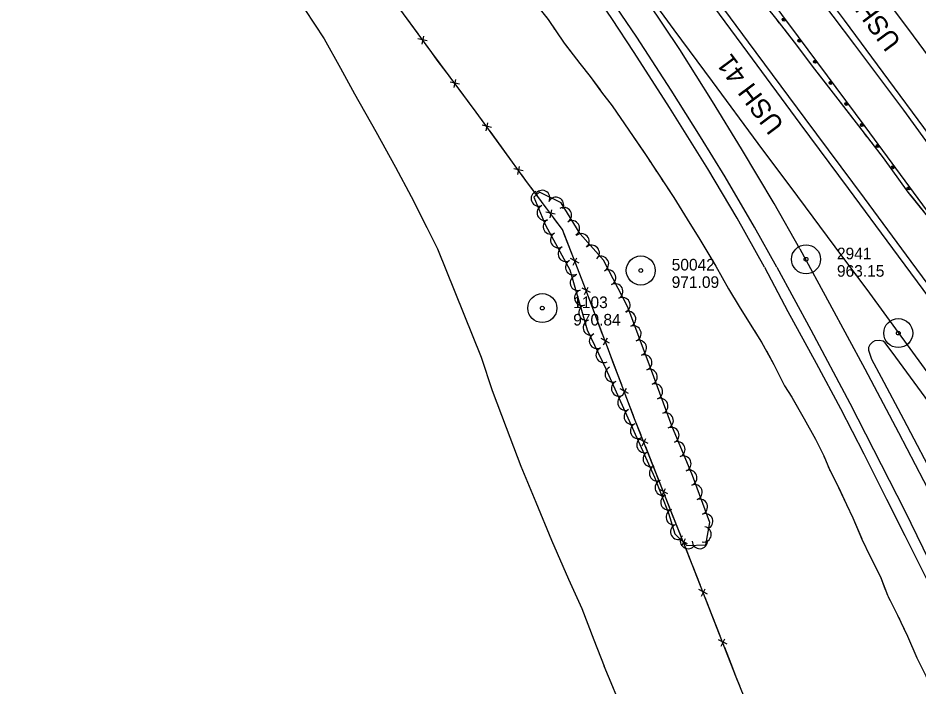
# Model space of a CAD drawing. Extents: x 353423 to 364002, y 127000 to 201942.
# Drawn here: x 358103.2 to 358569.3, y 133305.5 to 133651.2 of the extents above; entities that cross this region are included whole.
import ezdxf

# ---------------------------------------------------------------- set-up
doc = ezdxf.new("R2010")
doc.units = 0
for name, color, linetype in [('E_DTM_SlopeBottom', 7, 'Continuous'), ('E_DTM_SlopeTop', 7, 'Continuous'), ('E_FEN_Generic', 7, 'Continuous'), ('E_MISCPROP', 7, 'Continuous'), ('E_RDWY_AsphConc', 7, 'Continuous'), ('E_RW_IP', 7, 'Continuous'), ('E_STRUCT_WingWall', 7, 'Continuous')]:
    doc.layers.add(name, color=color, linetype=linetype)

msp = doc.modelspace()

# ---------------------------------------------------------------- linework, layer by layer
at = {"layer": 'E_DTM_SlopeBottom'}
for p, q in [((358314.93, 133639.42), (358310.13, 133640.52)), ((358312.21, 133637.66), (358313.14, 133641.78)), ((358331.53, 133617.07), (358326.71, 133618.11)), ((358328.83, 133615.27), (358329.7, 133619.41)), ((358348.11, 133594.66), (358343.3, 133595.76)), ((358345.4, 133592.89), (358346.31, 133597.02)), ((358364.53, 133572.15), (358359.72, 133573.25)), ((358361.81, 133570.38), (358362.72, 133574.51)), ((358378.43, 133548), (358379.3, 133552.14)), ((358381.12, 133549.8), (358376.3, 133550.84)), ((358393.46, 133524.54), (358389.1, 133526.84)), ((358390.38, 133523.53), (358392.33, 133527.28)), ((358399.34, 133509.27), (358394.99, 133511.6)), ((358396.25, 133508.28), (358398.23, 133512.02)), ((358409.2, 133483.22), (358404.86, 133485.55)), ((358406.11, 133482.23), (358408.09, 133485.97)), ((358419.07, 133457.16), (358414.72, 133459.49)), ((358415.98, 133456.17), (358417.95, 133459.91)), ((358429.12, 133431.21), (358424.74, 133433.47)), ((358426.05, 133430.17), (358427.97, 133433.94)), ((358439.38, 133405.3), (358435, 133407.57)), ((358436.3, 133404.27), (358438.22, 133408.04)), ((358449.63, 133379.4), (358445.25, 133381.66)), ((358446.56, 133378.37), (358448.48, 133382.13)), ((358456.76, 133352.45), (358458.69, 133356.21)), ((358459.83, 133353.47), (358455.46, 133355.75)), ((358470, 133327.53), (358465.63, 133329.81)), ((358466.92, 133326.51), (358468.85, 133330.27))]:
    msp.add_line(p, q, dxfattribs=at)
for points in [[(358395.86, 133513.55), (358384.88, 133541.86), (358366.84, 133566.02), (358340.28, 133602.45), (358317.22, 133633.32), (358288.05, 133673.47), (358260.09, 133711.16), (358241.9, 133736.28), (358214.23, 133774.01), (358187.7, 133809.56), (358155.49, 133852.29), (358125.09, 133893.37), (358100.76, 133925.95)], [(358310.34, 133642.79), (358303.68, 133651.95)], [(358320.11, 133629.44), (358317.22, 133633.32), (358314.21, 133637.46)], [(358326.89, 133620.38), (358320.11, 133629.44)], [(358336.79, 133607.13), (358330.83, 133615.1)], [(358343.51, 133598.02), (358340.28, 133602.45), (358336.79, 133607.13)], [(358353.26, 133584.65), (358347.39, 133592.7)], [(358359.93, 133575.51), (358353.26, 133584.65)], [(358369.72, 133562.18), (358366.84, 133566.02), (358363.8, 133570.19)], [(358376.49, 133553.1), (358369.72, 133562.18)], [(358385.79, 133539.52), (358384.88, 133541.86), (358380.42, 133547.83)], [(358389.88, 133528.97), (358385.79, 133539.52)], [(358395.86, 133513.55), (358392.26, 133522.83)], [(358725.68, 132583.74), (358758.72, 132601.14), (358713.52, 132713.04), (358681.9, 132791.31), (358650.4, 132872.83), (358629.23, 132926.93), (358604.43, 132991.52), (358574.94, 133062.09), (358555.62, 133108.12), (358526.45, 133181.6), (358502.84, 133241.38), (358474.77, 133310.6), (358451.95, 133368.81), (358422.16, 133444.07), (358395.86, 133513.55)], [(358401.65, 133498.26), (358398.12, 133507.57)], [(358405.66, 133487.67), (358401.65, 133498.26)], [(358411.51, 133472.2), (358407.99, 133481.52)], [(358415.52, 133461.61), (358411.51, 133472.2)], [(358421.38, 133446.15), (358417.85, 133455.46)], [(358425.51, 133435.61), (358422.16, 133444.07), (358421.38, 133446.15)], [(358431.6, 133420.23), (358427.93, 133429.49)], [(358435.77, 133409.71), (358431.6, 133420.23)], [(358441.85, 133394.33), (358438.19, 133403.58)], [(358446.02, 133383.8), (358441.85, 133394.33)], [(358452.11, 133368.42), (358451.95, 133368.81), (358448.44, 133377.68)], [(358456.24, 133357.88), (358452.11, 133368.42)], [(358462.27, 133342.48), (358458.64, 133351.75)], [(358466.4, 133331.94), (358462.27, 133342.48)], [(358472.43, 133316.54), (358468.8, 133325.81)], [(358476.62, 133306.02), (358474.77, 133310.6), (358472.43, 133316.54)]]:
    msp.add_lwpolyline(points, dxfattribs=at)
at = {"layer": 'E_DTM_SlopeTop'}
for points in [[(358410.49, 133650.87), (358393.29, 133676.15), (358374.38, 133703.52), (358357.7, 133727.25), (358339.4, 133753.66), (358320.07, 133781.45), (358301.48, 133808.44), (358281.55, 133836.86), (358261.2, 133866.08), (358242.57, 133892.57), (358225.2, 133917.27), (358205.5, 133944.9), (358188.78, 133968.59), (358169.81, 133995.17), (358151.76, 134021.41), (358131.7, 134049.96), (358113.99, 134074.7), (358093.46, 134101.84)], [(358426.57, 133830.55), (358455.05, 133791.84), (358479.58, 133758.58), (358507.67, 133720.69), (358533.77, 133685.63), (358563.82, 133645.18), (358591.92, 133607.24), (358620.28, 133568.8), (358651.43, 133527.05)], [(358421.8, 133796.91), (358440.49, 133771.76), (358463.67, 133740.46), (358489.34, 133705.62), (358510.41, 133677.2), (358530.62, 133650.15), (358550.56, 133623.09), (358574.61, 133590.7), (358603.57, 133551.18), (358618.85, 133530.92)], [(358421.37, 133792.31), (358440.23, 133766.89), (358466.21, 133731.29), (358489.88, 133699.28), (358513.44, 133667.16), (358535.92, 133637.33), (358561.21, 133603.52), (358589.09, 133565.36), (358616.3, 133528.83)], [(358565.29, 133525.4), (358541.03, 133558.06), (358510.34, 133599.27), (358481.16, 133638.63), (358452.68, 133677.28), (358424.75, 133715.06), (358416.24, 133726.44)], [(358555.73, 133532.13), (358532.82, 133563.11), (358507.85, 133596.75), (358480.83, 133633.44), (358446.14, 133680.37), (358415.27, 133722.02)], [(358507.58, 133531.89), (358494.31, 133555.34), (358477.47, 133583.53), (358462.46, 133608.12), (358445.56, 133634.89), (358429.04, 133659.55), (358415.74, 133679.56)], [(358525.9, 133532.85), (358506.55, 133559.03), (358486.13, 133586.41), (358462.41, 133618.37), (358442.63, 133645.15), (358425.18, 133669), (358416.3, 133681.05)], [(358495.74, 133522.42), (358484.2, 133543.1), (358468.98, 133569.05), (358456.29, 133589.84), (358441.07, 133613.89), (358423.35, 133641.37), (358410.07, 133660.92)], [(358489.45, 133522.39), (358475.21, 133547.74), (358460.04, 133573.21), (358440.29, 133604.98), (358422.04, 133633.39), (358410.49, 133650.87)], [(358507.58, 133531.89), (358522.97, 133503.62), (358541.24, 133469.91), (358558.64, 133436.92), (358575.88, 133403.94), (358595.91, 133363.41), (358611.43, 133330.23), (358626.82, 133295.4), (358639.31, 133265.7), (358653.53, 133230.18), (358666.74, 133196.82), (358683.23, 133152.94), (358700.55, 133105.45), (358718.16, 133055.76), (358734.3, 133010.39), (358748.67, 132970.84), (358764.44, 132926.36), (358782.23, 132877.05), (358799.21, 132829.36), (358817.4, 132778.22), (358831.07, 132739.51), (358843.74, 132704.12), (358858.57, 132662.25), (358864.5, 132645.91)], [(359014.98, 132872.22), (358990.58, 132905.27), (358965.96, 132938.61), (358942.42, 132970.37), (358917.38, 133004.54), (358891.3, 133039.88), (358860.54, 133081.26), (358828.86, 133123.8), (358802.79, 133159.2), (358774.67, 133197), (358755.44, 133223.24), (358708.14, 133287.06), (358678.19, 133327.54), (358651.91, 133363.16), (358625.83, 133398.17), (358597.71, 133435.92), (358572.17, 133470.31), (358543.84, 133508.94), (358525.9, 133532.85)], [(359149.33, 132730.14), (359141.98, 132740.02), (359121.46, 132767.94), (359094.32, 132804.79), (359065.49, 132843.54), (359041.09, 132876.48), (359013.99, 132913.16), (358986.74, 132950.18), (358957.65, 132989.48), (358930.02, 133026.89), (358903.35, 133063.01), (358876.85, 133098.64), (358852.29, 133132.02), (358827.39, 133165.47), (358799.27, 133203.16), (358770.72, 133241.91), (358742.22, 133280.32), (358712.97, 133319.96), (358683.29, 133360.05), (358650.11, 133404.77), (358618.43, 133447.54), (358590.64, 133485.12), (358555.73, 133532.13)], [(359041.87, 132881.2), (359018.38, 132913.08), (358997.26, 132941.39), (358970.11, 132978.07), (358944.47, 133012.74), (358922.43, 133042.39), (358898.46, 133074.83), (358873.47, 133108.61), (358849.55, 133140.93), (358827.25, 133171.08), (358805.7, 133200.17), (358778.28, 133237.36), (358748.71, 133277.33), (358723.12, 133311.67), (358696.19, 133348.52), (358673.89, 133378.89), (358646.53, 133415.63), (358615.81, 133456.78), (358589.15, 133493.02), (358565.29, 133525.4)], [(358489.45, 133522.39), (358501.46, 133499.47), (358516.05, 133472.87), (358528.66, 133449.34), (358540.82, 133425.87), (358552.49, 133402.57), (358562.03, 133383.67), (358574.34, 133358.87), (358586.93, 133331.7), (358600.16, 133302.42), (358609.85, 133279.65), (358621.92, 133250.73), (358634.51, 133219.64), (358643.86, 133196.44), (358660.73, 133151.45), (358672.67, 133118.66), (358683.47, 133089.15), (358695.3, 133056.1), (358709.23, 133016.83), (358725.44, 132972.34), (358737.91, 132937.62), (358752.6, 132897.46), (358766.73, 132856.87)], [(358495.74, 133522.42), (358513.32, 133490.04), (358533.45, 133452.15), (358562.03, 133396.49), (358574.33, 133371.03), (358588.9, 133340.18), (358603.35, 133308.35), (358619.73, 133270.64), (358630.41, 133244.27), (358640.77, 133218.3), (358645.89, 133205.2), (358667.41, 133148.99), (358678.57, 133118.59), (358690.35, 133085.59), (358701.88, 133053.76), (358719.23, 133004.84), (358736.64, 132956.36), (358751.53, 132915.54), (358763.42, 132882.31)], [(358574.36, 133452.6), (358557.4, 133475.93), (358551.85, 133483.36), (358550.71, 133484.26), (358548.84, 133484.51), (358546.46, 133484.28), (358545.24, 133483.69), (358543.84, 133482.34), (358543.15, 133480.86), (358543.13, 133479.54), (358544.7, 133474.94), (358549.78, 133465.54), (358561.2, 133443.9), (358578.97, 133410.08)]]:
    msp.add_lwpolyline(points, dxfattribs=at)
at = {"layer": 'E_FEN_Generic'}
msp.add_lwpolyline([(358407.35, 133469.82), (358432.42, 133413.93), (358439.65, 133395.23), (358442.94, 133384.57), (358449.28, 133378.53), (358458.96, 133378.96), (358461.1, 133390.45), (358452.19, 133414.77), (358441.44, 133440.48), (358430.91, 133468.99), (358418.75, 133501.76), (358406.11, 133526.07), (358393.96, 133539.67), (358384.15, 133555.62), (358373.05, 133561.15), (358370.12, 133558.57), (358376.15, 133544.05), (358388.73, 133521.11), (358397.69, 133490.08)], close=True, dxfattribs=at)
for centre, start, end in [((358372.66, 133557.91), 112.5447, 292.5294), ((358374.36, 133558.16), 333.5076, 153.4923), ((358381.52, 133554.59), 333.5076, 153.4923), ((358375.73, 133550.52), 112.5447, 292.5294), ((358385.57, 133549.32), 301.632, 121.6166), ((358378.88, 133543.42), 118.7433, 298.728), ((358389.76, 133542.51), 301.632, 121.6166), ((358382.72, 133536.41), 118.7433, 298.728), ((358394.65, 133535.76), 311.761, 131.7456), ((358399.98, 133529.79), 311.761, 131.7456), ((358386.57, 133529.4), 118.7433, 298.728), ((358390.41, 133522.38), 118.7433, 298.728), ((358404.78, 133524.09), 297.4904, 117.4751), ((358408.47, 133516.99), 297.4904, 117.4751), ((358392.87, 133514.3), 106.1242, 286.1089), ((358395.09, 133506.61), 106.1242, 286.1089), ((358412.16, 133509.9), 297.4904, 117.4751), ((358415.85, 133502.8), 297.4904, 117.4751), ((358397.31, 133498.93), 106.1242, 286.1089), ((358418.79, 133495.65), 290.3583, 110.343), ((358399.53, 133491.24), 106.1242, 286.1089), ((358421.57, 133488.15), 290.3583, 110.343), ((358402.76, 133484.31), 115.4897, 295.4744), ((358424.35, 133480.65), 290.3583, 110.343), ((358406.2, 133477.09), 115.4897, 295.4744), ((358427.13, 133473.15), 290.3583, 110.343), ((358410.89, 133467.03), 114.1677, 294.1524), ((358429.91, 133465.65), 290.2885, 110.2732), ((358414.17, 133459.73), 114.1677, 294.1524), ((358432.68, 133458.15), 290.2885, 110.2732), ((358417.44, 133452.43), 114.1677, 294.1524), ((358435.45, 133450.65), 290.2885, 110.2732), ((358420.72, 133445.13), 114.1677, 294.1524), ((358438.23, 133443.14), 290.2885, 110.2732), ((358423.99, 133437.83), 114.1677, 294.1524), ((358441.2, 133435.63), 292.7008, 112.6854), ((358427.26, 133430.54), 114.1677, 294.1524), ((358444.29, 133428.25), 292.7008, 112.6854), ((358430.54, 133423.24), 114.1677, 294.1524), ((358447.38, 133420.87), 292.7008, 112.6854), ((358433.81, 133415.94), 114.1677, 294.1524), ((358450.41, 133413.57), 290.1263, 110.111), ((358436.8, 133408.4), 111.1379, 291.1226), ((358453.16, 133406.06), 290.1263, 110.111), ((358439.68, 133400.94), 111.1379, 291.1226), ((358455.91, 133398.54), 290.1263, 110.111), ((358442.44, 133393.28), 107.181, 287.1656), ((358458.66, 133391.03), 290.1263, 110.111), ((358444.8, 133385.64), 107.181, 287.1656), ((358457.83, 133384.34), 259.4226, 79.4072), ((358449.83, 133380.89), 136.3748, 316.3594), ((358455.95, 133380.92), 182.5352, 2.5199)]:
    msp.add_arc(centre, 4, start, end, dxfattribs=at)
at = {"layer": 'E_MISCPROP'}
for points in [[(358589.51, 133529.9), (358541.37, 133595.12), (358507, 133641.39), (358471.88, 133688.48), (358424.14, 133753.4)], [(358589.51, 133529.9), (358541.37, 133595.12), (358507, 133641.39), (358471.88, 133688.48), (358424.14, 133753.4)], [(358251.66, 133655.67), (358261.55, 133640.36), (358270.03, 133625.19), (358277.26, 133611.99), (358288.3, 133592.47), (358298.57, 133574.13), (358306.56, 133558.89), (358314.7, 133542.85), (358320.19, 133531.91)], [(358320.19, 133531.91), (358342.78, 133475.85), (358348.49, 133458.61), (358355.67, 133439.57), (358363.34, 133419.65), (358371.11, 133400.93), (358379.2, 133381.38), (358387.94, 133361.12), (358394.92, 133345.98), (358401.14, 133329.81), (358406.51, 133316.14)], [(358443.57, 133247.22), (358436.22, 133252.47), (358428.71, 133264.4), (358418.61, 133286.51), (358410.95, 133305.49), (358406.51, 133316.14)]]:
    msp.add_lwpolyline(points, dxfattribs=at)
for centre, radius in [((358499.34, 133650.35), 0.79), ((358499.31, 133650.38), 0.398), ((358507.44, 133639.47), 0.79), ((358507.42, 133639.51), 0.398), ((358515.53, 133628.59), 0.79), ((358515.5, 133628.62), 0.398), ((358523.62, 133617.7), 0.79), ((358523.59, 133617.73), 0.398), ((358531.7, 133606.81), 0.79), ((358531.68, 133606.84), 0.398), ((358539.79, 133595.92), 0.79), ((358539.76, 133595.96), 0.398), ((358547.85, 133585.01), 0.79), ((358547.82, 133585.05), 0.398), ((358555.9, 133574.1), 0.79), ((358555.88, 133574.14), 0.398), ((358563.96, 133563.19), 0.79), ((358563.93, 133563.23), 0.398)]:
    msp.add_circle(centre, radius, dxfattribs=at)
at = {"layer": 'E_RDWY_AsphConc'}
for centre, radius in [((358510.86, 133526.49), 7.5), ((358510.86, 133526.49), 7.5), ((358510.86, 133526.49), 7.5), ((358425.37, 133520.7), 7.5), ((358425.37, 133520.7), 7.5), ((358425.37, 133520.7), 7.5), ((358425.37, 133520.7), 7.5), ((358510.86, 133526.49), 0.96), ((358510.86, 133526.49), 0.96), ((358510.86, 133526.49), 0.96), ((358425.37, 133520.7), 0.96), ((358425.37, 133520.7), 0.96), ((358425.37, 133520.7), 0.96), ((358425.37, 133520.7), 0.96), ((358374.44, 133501.27), 7.5), ((358374.44, 133501.27), 7.5), ((358374.44, 133501.27), 7.5), ((358374.44, 133501.27), 7.5), ((358374.44, 133501.27), 0.96), ((358374.44, 133501.27), 0.96), ((358374.44, 133501.27), 0.96), ((358374.44, 133501.27), 0.96), ((358558.59, 133488.36), 7.5), ((358558.59, 133488.36), 7.5), ((358558.59, 133488.36), 0.96), ((358558.59, 133488.36), 0.96)]:
    msp.add_circle(centre, radius, dxfattribs=at)
at = {"layer": 'E_STRUCT_WingWall'}
for points in [[(358419.08, 133748.73), (358430.22, 133736.2), (358441.95, 133720.9), (358453.51, 133705.11), (358465.23, 133688.51), (358474.69, 133675.99), (358485.01, 133663.68), (358495.72, 133650.18), (358504.69, 133638.74), (358515.17, 133624.81), (358526.09, 133610.82), (358537.93, 133595.52), (358550.73, 133578.91), (358563.59, 133561.17), (358577.76, 133543.41), (358588.46, 133529.48)], [(358312.81, 133744.69), (358316.61, 133740.7), (358319.54, 133735.64), (358322.91, 133729.34), (358326.55, 133722.44), (358329.42, 133715.73), (358332.24, 133709.01), (358336.18, 133701.99), (358340.01, 133696.34), (358344.99, 133690.1), (358350.72, 133683.31), (358355.82, 133676.81), (358360.64, 133670.2), (358366.08, 133664.32), (358370.71, 133658.91), (358377.45, 133650.45), (358385.68, 133638.27), (358393.89, 133627.63), (358399.2, 133620.92), (358405.12, 133612.93), (358410.55, 133605.8)], [(358376.18, 133652.03), (358377.43, 133650.47)], [(358495.77, 133650.12), (358497, 133648.54)], [(358379.67, 133647.16), (358380.79, 133645.5)], [(358499.47, 133645.4), (358504.69, 133638.74), (358515.17, 133624.81), (358517.08, 133622.36)], [(358383.03, 133642.18), (358384.15, 133640.53)], [(358386.46, 133637.26), (358393.89, 133627.63), (358399.2, 133620.92), (358404.12, 133614.27)], [(358517.08, 133622.36), (358526.09, 133610.82), (358534.88, 133599.46)], [(358404.12, 133614.27), (358405.12, 133612.93), (358410.55, 133605.8)], [(358410.55, 133605.8), (358419.24, 133593.23), (358427.08, 133581.75), (358434.47, 133570.54), (358442.47, 133558.35), (358449.38, 133547.3), (358455.85, 133536.74), (358464.29, 133522.96)], [(358410.55, 133605.8), (358419.24, 133593.23), (358426.97, 133581.9)], [(358537.32, 133596.3), (358537.93, 133595.52), (358538.55, 133594.71)], [(358540.99, 133591.55), (358542.21, 133589.96)], [(358544.65, 133586.79), (358545.88, 133585.21)], [(358548.32, 133582.04), (358550.73, 133578.91), (358563.59, 133561.17), (358565.54, 133558.72)], [(358429.17, 133578.57), (358430.28, 133576.9)], [(358432.48, 133573.56), (358433.58, 133571.89)], [(358435.78, 133568.55), (358436.87, 133566.87)], [(358439.07, 133563.53), (358442.47, 133558.35), (358449.38, 133547.3), (358454.49, 133538.97)], [(358565.54, 133558.72), (358577.76, 133543.41), (358583.49, 133535.94)], [(358454.49, 133538.97), (358455.85, 133536.74), (358464.29, 133522.96)], [(358464.29, 133522.96), (358470.82, 133511.27), (358476.28, 133502.13), (358481.97, 133493), (358487.87, 133483.69), (358494.17, 133472.06), (358499.66, 133461.11), (358503.48, 133455.25), (358509.9, 133444.01), (358515.72, 133433.49), (358519.99, 133424.98), (358523.01, 133417.77), (358527.59, 133408.7), (358531.79, 133399.81), (358535.04, 133392.92), (358539.75, 133381.87), (358544.12, 133372.92), (358549.34, 133362.36), (358552.98, 133352.87), (358558.2, 133342.63), (358563.3, 133331.63), (358568.24, 133320.58), (358572.82, 133311.24)], [(358464.29, 133522.96), (358470.82, 133511.27), (358476.28, 133502.13), (358478.91, 133497.91)], [(358481.02, 133494.52), (358481.97, 133493), (358482.08, 133492.82)], [(358484.22, 133489.44), (358485.29, 133487.75)], [(358487.43, 133484.38), (358487.87, 133483.69), (358488.43, 133482.65)], [(358490.34, 133479.13), (358494.17, 133472.06), (358499.66, 133461.11), (358503.48, 133455.25), (358504.33, 133453.76)], [(358504.33, 133453.76), (358509.9, 133444.01), (358515.72, 133433.49), (358518.3, 133428.35)], [(358520.08, 133424.77), (358520.85, 133422.92)], [(358522.39, 133419.23), (358523.01, 133417.77), (358523.19, 133417.4)], [(358524.99, 133413.83), (358525.9, 133412.05)], [(358527.7, 133408.47), (358531.79, 133399.81), (358535.04, 133392.92), (358539.67, 133382.07)], [(358539.67, 133382.07), (358539.75, 133381.87), (358544.12, 133372.92), (358549.34, 133362.36), (358551.86, 133355.78)], [(358553.38, 133352.08), (358554.29, 133350.3)], [(358556.11, 133346.74), (358557.02, 133344.96)], [(358558.79, 133341.37), (358559.63, 133339.56)], [(358561.31, 133335.93), (358563.3, 133331.63), (358568.24, 133320.58), (358572.82, 133311.24), (358573.57, 133309.65)]]:
    msp.add_lwpolyline(points, dxfattribs=at)

# ---------------------------------------------------------------- texts
at = {"layer": 'E_RDWY_AsphConc'}
for s, p in [('2941', (358526.86, 133526.49)), ('2941', (358526.86, 133526.49)), ('2941', (358526.86, 133526.49)), ('50042', (358441.37, 133520.7)), ('50042', (358441.37, 133520.7)), ('50042', (358441.37, 133520.7)), ('50042', (358441.37, 133520.7)), ('963.15', (358526.86, 133517.49)), ('963.15', (358526.86, 133517.49)), ('963.15', (358526.86, 133517.49)), ('971.09', (358441.37, 133511.7)), ('971.09', (358441.37, 133511.7)), ('971.09', (358441.37, 133511.7)), ('971.09', (358441.37, 133511.7)), ('1103', (358390.44, 133501.27)), ('1103', (358390.44, 133501.27)), ('1103', (358390.44, 133501.27)), ('1103', (358390.44, 133501.27)), ('970.84', (358390.44, 133492.27)), ('970.84', (358390.44, 133492.27)), ('970.84', (358390.44, 133492.27)), ('970.84', (358390.44, 133492.27))]:
    msp.add_text(s, height=6, dxfattribs=at).set_placement(p)
at = {"layer": 'E_RW_IP'}
for rotation, p in [(126.3878, (358560.48, 133638.92)), (126.7201, (358499.96, 133595.95))]:
    msp.add_text('USH 41', height=10, rotation=rotation, dxfattribs=at).set_placement(p)

doc.saveas('drawing.dxf')
